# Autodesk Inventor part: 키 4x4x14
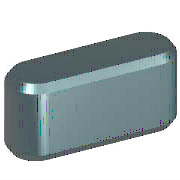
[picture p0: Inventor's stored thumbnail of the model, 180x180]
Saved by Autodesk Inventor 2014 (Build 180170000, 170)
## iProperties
IsCustomPart: 1
Created: 2012-02
Part Number: 키 4x4x14
Material: 강철, 연강
Description: 키 및 해당 키홈
Document SubType Name: Modeling
Standard: KS B 1311
Designer: mduedu
Standards Organization: KS
Language: ko-KR
Size Designation: 4 x 4 x 14
Categories: <MemberInstance><Categories><Category DisplayName="샤프트 부품" InternalName="7f7aeb1f-a693-4053-b835-cee3144e0d98" Mnemonic="SHFT"><Category DisplayName="키" Interna
Density: 1 g/cm^3
Appearance: Yellow
Author: mduedu
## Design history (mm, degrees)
sketch "스케치1"
  geometry: L1 (2, 2)-(12, 2); L2 (12, -2)-(2, -2); L3 (0, 9.4)-(0, -7.4) reference; L4 (-5, 0)-(30, 0) reference; L5 (14, 0)-(14, 7); A1 r 2 centre (2, 0) between (2, 2) and (2, -2); A2 r 2 centre (12, 0) between (12, -2) and (12, 2)
  constraints: 6 end point, 5 point on circle, 4 tangent, 3 point on line, 2 centre point, 1 horizontal, 1 parallel, 1 perpendicular
  dimensions: "d0" = 2 radius of A1 (= 0.5 x PB); "d13" = 2 radius of A2 (= 0.5 x PB); "d14" = 14 distance between parallel lines of L5 L3 (= NLG)
extrude "본체1" new body sketch "스케치1" taper "d3" = 0 deg; stored distance "d4" = 10
workplane "Work Plane3"
body "Solid1"
workplane "Work Plane1"
workplane "Work Plane2"
chamfer "모따기1" distance "d8" = 0.25 (= PHH); stored, may be unused: second distance "d9" = 0.25 (= PHH), angle "d15" = 45 deg
other parameters: "d1" = -2.5 (= -PNT), "d2" = 1.5 (= PH - PNT), "NLG" = 14 [user parameter; used in 3 equation terms], "PB" = 4 [user parameter; used in 2 equation terms], "PNT" = 2.5 [user parameter; used in 2 equation terms], "PH" = 4 [user parameter; used in 1 equation term], "PHH" = 0.25 [user parameter; used in 2 equation terms], "d10" = 0, "d16" = 0, "d17" = 0, "d18" = 0, "PLB2" = 14 (= NLG) [user parameter], "WDMAX" = 12 [user parameter], "PLB1" = 14 (= NLG) [user parameter], "RR" = 0.08 [user parameter], "PUEB" = 1.8 [user parameter]
